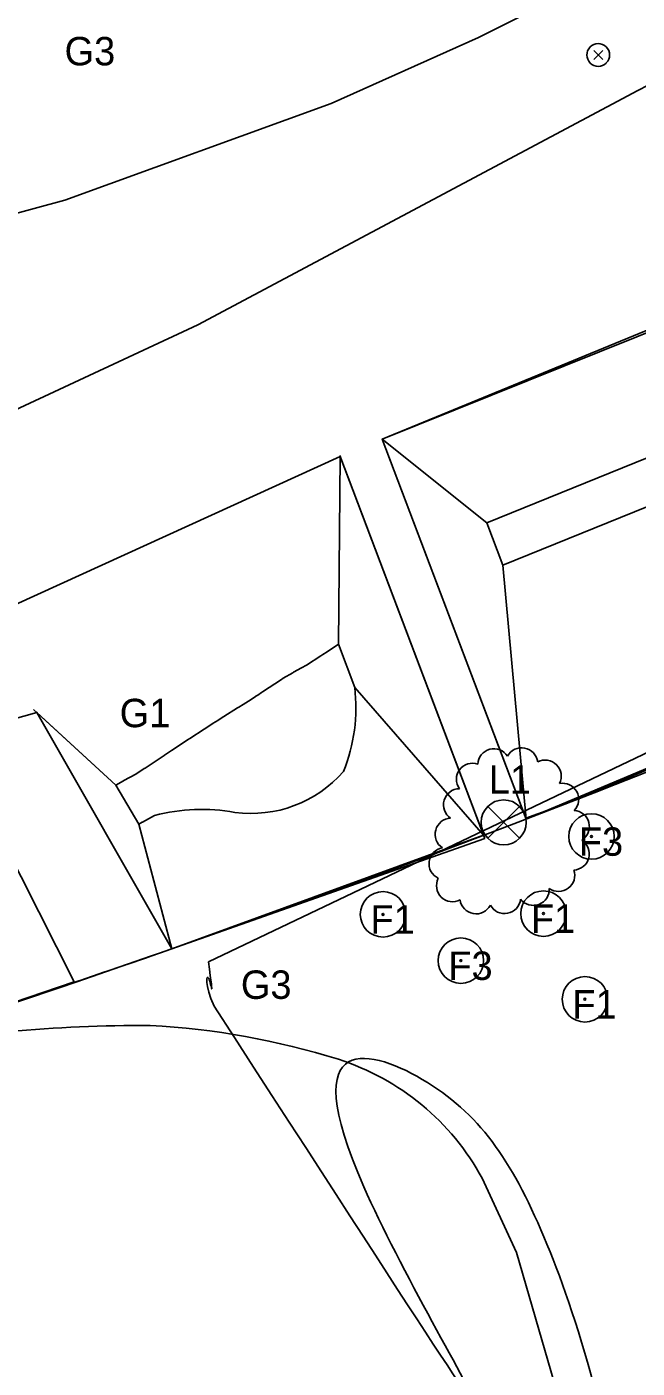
# Model space of a CAD drawing. Extents: x 0 to 512122, y 0 to 6212554.
# Drawn here: x 511701 to 511727.9, y 6211766.1 to 6211825.1 of the extents above; entities that cross this region are included whole.
import ezdxf

# ---------------------------------------------------------------- set-up
doc = ezdxf.new("R2010")
doc.units = 0
for name, color, linetype in [('_lights', 7, 'Continuous'), ('_Låge L1', 7, 'Continuous'), ('_LØ1', 7, 'Continuous'), ('_ny fruit trees', 7, 'Continuous'), ('Clouds', 7, 'Continuous'), ('L40 jord udlagt muld og grøft', 7, 'Continuous'), ('MatrikelnummerMaster', 7, 'Continuous'), ('TV_U_AFM_Symbl_Gul', 7, 'Continuous')]:
    doc.layers.add(name, color=color, linetype=linetype)

msp = doc.modelspace()

# ---------------------------------------------------------------- linework, layer by layer
at = {"layer": '_lights'}
for p, q in [((511725.987, 6211824.104), (511726.381, 6211823.71)), ((511726.385, 6211824.108), (511725.991, 6211823.714))]:
    msp.add_line(p, q, dxfattribs=at)
for start, end in [(315.56363, 315), (315, 315.56363)]:
    msp.add_arc((511726.184, 6211823.907), 0.5, start, end, dxfattribs=at)
at = {"layer": '_Låge L1'}
for p, q in [((511722.723, 6211790.848), (511721.325, 6211789.45)), ((511721.325, 6211790.848), (511722.723, 6211789.45))]:
    msp.add_line(p, q, dxfattribs=at)
msp.add_circle((511722.024, 6211790.149), 0.989, dxfattribs=at)
at = {"layer": '_LØ1'}
msp.add_lwpolyline([(511692.013, 6211804.326), (511708.572, 6211812.03), (511727.934, 6211822.351), (511741.108, 6211829.168), (511739.062, 6211834.697), (511735.073, 6211832.201), (511727.568, 6211828.01), (511720.915, 6211824.671), (511714.441, 6211821.769), (511702.714, 6211817.514), (511693.252, 6211814.953)], dxfattribs=at)
at = {"layer": '_ny fruit trees'}
for centre, radius in [((511725.886, 6211789.528), 1), ((511725.886, 6211789.528), 0.0426), ((511716.716, 6211786.101), 1), ((511723.775, 6211786.135), 1), ((511716.716, 6211786.101), 0.0426), ((511723.775, 6211786.135), 0.0426), ((511720.143, 6211784.066), 1), ((511720.143, 6211784.066), 0.0426), ((511725.6, 6211782.366), 1), ((511725.6, 6211782.366), 0.0426)]:
    msp.add_circle(centre, radius, dxfattribs=at)
at = {"layer": 'Clouds'}
for centre, radius, start, end in [((511721.592, 6211792.678), 0.709, 32.24962, 177.24962), ((511722.817, 6211792.723), 0.709, 6.97767, 151.97767), ((511720.65, 6211792.043), 0.708, 70.72998, 215.72998), ((511723.851, 6211792.182), 0.709, 332.76117, 117.76117), ((511720.087, 6211790.92), 0.709, 91.03092, 236.03092), ((511724.618, 6211791.162), 0.709, 316.13462, 101.13462), ((511719.717, 6211789.624), 0.709, 92.12188, 237.12188), ((511725.087, 6211789.963), 0.709, 301.65692, 86.65692), ((511719.451, 6211788.329), 0.709, 99.60339, 244.60339), ((511725.082, 6211788.76), 0.709, 272.79342, 57.79342), ((511724.446, 6211787.82), 0.709, 234.07597, 19.07597), ((511719.777, 6211787.364), 0.708, 152.7449, 297.7449), ((511723.323, 6211787.206), 0.709, 218.23899, 3.23899), ((511720.809, 6211786.833), 0.709, 187.72661, 332.72661), ((511722.061, 6211786.847), 0.709, 208.55844, 353.55844)]:
    msp.add_arc(centre, radius, start, end, dxfattribs=at)
at = {"layer": 'L40 jord udlagt muld og grøft'}
for p, q in [((511716.684, 6211807.008), (511721.285, 6211803.326)), ((511723.011, 6211790.292), (511716.684, 6211807.008)), ((511721.992, 6211801.458), (511723.011, 6211790.293)), ((511714.753, 6211797.986), (511714.253, 6211797.657)), ((511715.47, 6211796.088), (511714.753, 6211797.986)), ((511712.754, 6211796.734), (511712.321, 6211796.485)), ((511712.784, 6211796.751), (511712.754, 6211796.734)), ((511710.917, 6211795.557), (511710.564, 6211795.334)), ((511701.486, 6211794.988), (511707.423, 6211784.585)), ((511710.564, 6211795.334), (511710.372, 6211795.221)), ((511709.319, 6211794.55), (511709.276, 6211794.522)), ((511709.376, 6211794.586), (511709.319, 6211794.55)), ((511706.434, 6211792.656), (511706.255, 6211792.538)), ((511705.294, 6211791.975), (511704.967, 6211791.786)), ((511704.967, 6211791.786), (511705.973, 6211790.068)), ((511704.967, 6211791.786), (511705.973, 6211790.068)), ((511704.967, 6211791.786), (511705.973, 6211790.068))]:
    msp.add_line(p, q, dxfattribs=at)
for points in [[(511716.684, 6211807.008), (511745.321, 6211818.788), (511750.168, 6211811.842), (511756.678, 6211804.446), (511723.011, 6211790.293), (511716.684, 6211807.008)], [(511714.834, 6211806.244), (511714.753, 6211797.986), (511715.47, 6211796.088), (511721.141, 6211789.582)], [(511721.196, 6211789.436), (511714.816, 6211806.291)], [(511714.753, 6211797.986), (511714.253, 6211797.657), (511714.075, 6211797.54), (511713.977, 6211797.476), (511713.348, 6211797.064), (511713.123, 6211796.942), (511712.784, 6211796.751), (511712.754, 6211796.734), (511712.753, 6211796.734), (511712.321, 6211796.485), (511712.255, 6211796.439), (511711.409, 6211795.887), (511711.363, 6211795.856), (511711.206, 6211795.751), (511711.122, 6211795.695), (511711.108, 6211795.685), (511710.917, 6211795.557), (511710.564, 6211795.334), (511710.372, 6211795.221), (511710.308, 6211795.183), (511709.708, 6211794.805), (511709.415, 6211794.611), (511709.376, 6211794.586), (511709.319, 6211794.55), (511709.276, 6211794.522), (511708.847, 6211794.243), (511708.216, 6211793.837), (511708.116, 6211793.775), (511707.963, 6211793.681), (511707.406, 6211793.308), (511707.109, 6211793.105), (511707.091, 6211793.093), (511706.918, 6211792.976), (511706.434, 6211792.656), (511706.255, 6211792.538), (511706.214, 6211792.512), (511705.835, 6211792.269), (511705.312, 6211791.985), (511705.294, 6211791.975), (511704.967, 6211791.786)], [(511714.753, 6211797.986), (511714.253, 6211797.657), (511714.075, 6211797.54), (511713.977, 6211797.476), (511713.348, 6211797.064), (511713.123, 6211796.942), (511712.784, 6211796.751), (511712.754, 6211796.734), (511712.753, 6211796.734), (511712.321, 6211796.485), (511712.255, 6211796.439), (511711.409, 6211795.887), (511711.363, 6211795.856), (511711.206, 6211795.751), (511711.122, 6211795.695), (511711.108, 6211795.685), (511710.917, 6211795.557), (511710.564, 6211795.334), (511710.372, 6211795.221), (511710.308, 6211795.183), (511709.708, 6211794.805), (511709.415, 6211794.611), (511709.376, 6211794.586), (511709.319, 6211794.55), (511709.276, 6211794.522), (511708.847, 6211794.243), (511708.216, 6211793.837), (511708.116, 6211793.775), (511707.963, 6211793.681), (511707.406, 6211793.308), (511707.109, 6211793.105), (511707.091, 6211793.093), (511706.918, 6211792.976), (511706.434, 6211792.656), (511706.255, 6211792.538), (511706.214, 6211792.512), (511705.835, 6211792.269), (511705.312, 6211791.985), (511705.294, 6211791.975), (511704.967, 6211791.786)], [(511714.753, 6211797.986), (511715.47, 6211796.088)], [(511713.977, 6211797.476), (511713.348, 6211797.064), (511713.123, 6211796.942), (511712.784, 6211796.751)], [(511714.253, 6211797.657), (511714.075, 6211797.54), (511713.977, 6211797.476)], [(511712.321, 6211796.485), (511712.255, 6211796.439), (511711.409, 6211795.887), (511711.363, 6211795.856), (511711.206, 6211795.751), (511711.122, 6211795.695)], [(511711.122, 6211795.695), (511711.108, 6211795.685), (511710.917, 6211795.557)], [(511701.343, 6211795.121), (511704.967, 6211791.786)], [(511710.372, 6211795.221), (511710.308, 6211795.183), (511709.708, 6211794.805)], [(511709.276, 6211794.522), (511708.847, 6211794.243), (511708.216, 6211793.837)], [(511709.708, 6211794.805), (511709.415, 6211794.611), (511709.376, 6211794.586)], [(511708.216, 6211793.837), (511708.116, 6211793.775), (511707.963, 6211793.681), (511707.406, 6211793.308), (511707.109, 6211793.105), (511707.091, 6211793.093)], [(511707.091, 6211793.093), (511706.918, 6211792.976), (511706.434, 6211792.656)], [(511699.055, 6211781.732), (511702.465, 6211782.876), (511703.242, 6211783.141), (511706.493, 6211784.259), (511706.884, 6211784.395), (511710.536, 6211785.681), (511710.878, 6211785.803), (511714.441, 6211787.088), (511714.832, 6211787.231), (511718.516, 6211788.591), (511719.148, 6211788.829), (511722.285, 6211790.014), (511722.477, 6211790.086), (511726.198, 6211791.523), (511726.45, 6211791.621), (511730.172, 6211793.09)], [(511706.255, 6211792.538), (511706.214, 6211792.512), (511705.835, 6211792.269)], [(511705.835, 6211792.269), (511705.312, 6211791.985), (511705.294, 6211791.975)], [(511705.973, 6211790.068), (511706.123, 6211790.155), (511706.141, 6211790.164), (511706.666, 6211790.45)], [(511705.973, 6211790.068), (511706.123, 6211790.155), (511706.141, 6211790.164), (511706.666, 6211790.45)], [(511705.973, 6211790.068), (511707.423, 6211784.585)], [(511721.196, 6211789.436), (511706.887, 6211784.396), (511706.495, 6211784.26), (511706.268, 6211784.181), (511705.488, 6211783.913), (511705.487, 6211783.913), (511705.304, 6211783.85), (511705.269, 6211783.838), (511704.536, 6211783.586), (511704.481, 6211783.567), (511703.648, 6211783.281), (511703.556, 6211783.249), (511703.475, 6211783.221), (511703.245, 6211783.142), (511702.468, 6211782.877), (511702.203, 6211782.788), (511702.184, 6211782.782), (511702.013, 6211782.724), (511701.773, 6211782.644), (511701.459, 6211782.539), (511700.924, 6211782.359)], [(511727.864, 6211745.992), (511724.951, 6211763.088), (511722.584, 6211771.227), (511721.08, 6211774.49)]]:
    msp.add_lwpolyline(points, dxfattribs=at)
for points in [[(511724.584, 6211790.9), (511722.995, 6211790.334), (511716.685, 6211807.008), (511745.435, 6211818.563), (511747.247, 6211815.371), (511749.591, 6211811.924), (511752.478, 6211808.405), (511754.722, 6211806.079), (511756.429, 6211804.372), (511725.419, 6211791.222)], [(511721.285, 6211803.326), (511742.452, 6211811.904), (511743.388, 6211810.13), (511721.992, 6211801.458)], [(511723.011, 6211790.293), (511716.684, 6211807.008), (511721.285, 6211803.326), (511721.992, 6211801.458)], [(511697.82, 6211781.325), (511690.461, 6211779.381), (511688.599, 6211783.339), (511688.247, 6211785.796), (511688.218, 6211788.948), (511688.919, 6211791.428), (511690.581, 6211794.293), (511692.017, 6211795.84), (511714.827, 6211806.237), (511721.141, 6211789.582), (511707.423, 6211784.585), (511701.486, 6211794.988), (511697.668, 6211793.905), (511703.13, 6211783.132)], [(511721.141, 6211789.582), (511715.47, 6211796.088), (511714.753, 6211797.986), (511714.834, 6211806.244)], [(511707.423, 6211784.585), (511701.486, 6211794.988), (511704.967, 6211791.786), (511705.973, 6211790.068)]]:
    msp.add_lwpolyline(points, close=True, dxfattribs=at)
for centre, radius, start, end in [((511708.029, 6211795.204), 7.494, 337.90338, 6.78043), ((511708.029, 6211795.204), 7.494, 337.90338, 6.78043), ((511710.915, 6211795.928), 5.387, 262.3726, 318.86566), ((511710.915, 6211795.928), 5.387, 262.3726, 318.86566), ((511708.744, 6211782.585), 8.135, 79.69101, 104.80076), ((511708.744, 6211782.585), 8.135, 79.69101, 104.80076), ((511706.235, 6211714.219), 66.997, 89.79266, 100.43613), ((511704.634, 6211747.267), 33.999, 72.68221, 86.89164), ((511711.411, 6211769.245), 11, 28.47603, 72.30609)]:
    msp.add_arc(centre, radius, start, end, dxfattribs=at)
at = {"layer": 'MatrikelnummerMaster'}
msp.add_lwpolyline([(511709.039, 6211784.02), (511731.329, 6211794.65), (511753.839, 6211806.083), (511755.583, 6211803.583), (511754.025, 6211802.931), (511749.976, 6211800.563), (511746.182, 6211797.81), (511742.241, 6211794.091), (511738.319, 6211789.251), (511735.288, 6211783.752), (511733.159, 6211777.92), (511731.942, 6211773.006), (511731.564, 6211766.894), (511731.842, 6211762.252), (511732.411, 6211756.897), (511733.074, 6211752.945), (511728.666, 6211752.117)], dxfattribs=at)
for points in [[(511709.29, 6211782.06), (511708.842, 6211783.005), (511709.039, 6211784.02), (511709.29, 6211782.06), (511709.039, 6211784.02)], [(511728.666, 6211752.117), (511726.887, 6211763.158), (511723.863, 6211773.002), (511719.725, 6211779.29), (511709.29, 6211782.06), (511728.666, 6211752.117), (511709.29, 6211782.06)]]:
    msp.add_open_spline(points, degree=3, dxfattribs=at)

# ---------------------------------------------------------------- texts
at = {"layer": 'TV_U_AFM_Symbl_Gul'}
for s, p in [('G3', (511702.704, 6211823.45)), ('G1', (511705.13, 6211794.335)), ('L1', (511721.367, 6211791.413)), ('F3', (511725.331, 6211788.679)), ('F1', (511716.161, 6211785.252)), ('F1', (511723.22, 6211785.286)), ('F3', (511719.588, 6211783.217)), ('G3', (511710.461, 6211782.384)), ('F1', (511725.045, 6211781.518))]:
    msp.add_text(s, height=1.25, dxfattribs=at).set_placement(p)

doc.saveas('drawing.dxf')
